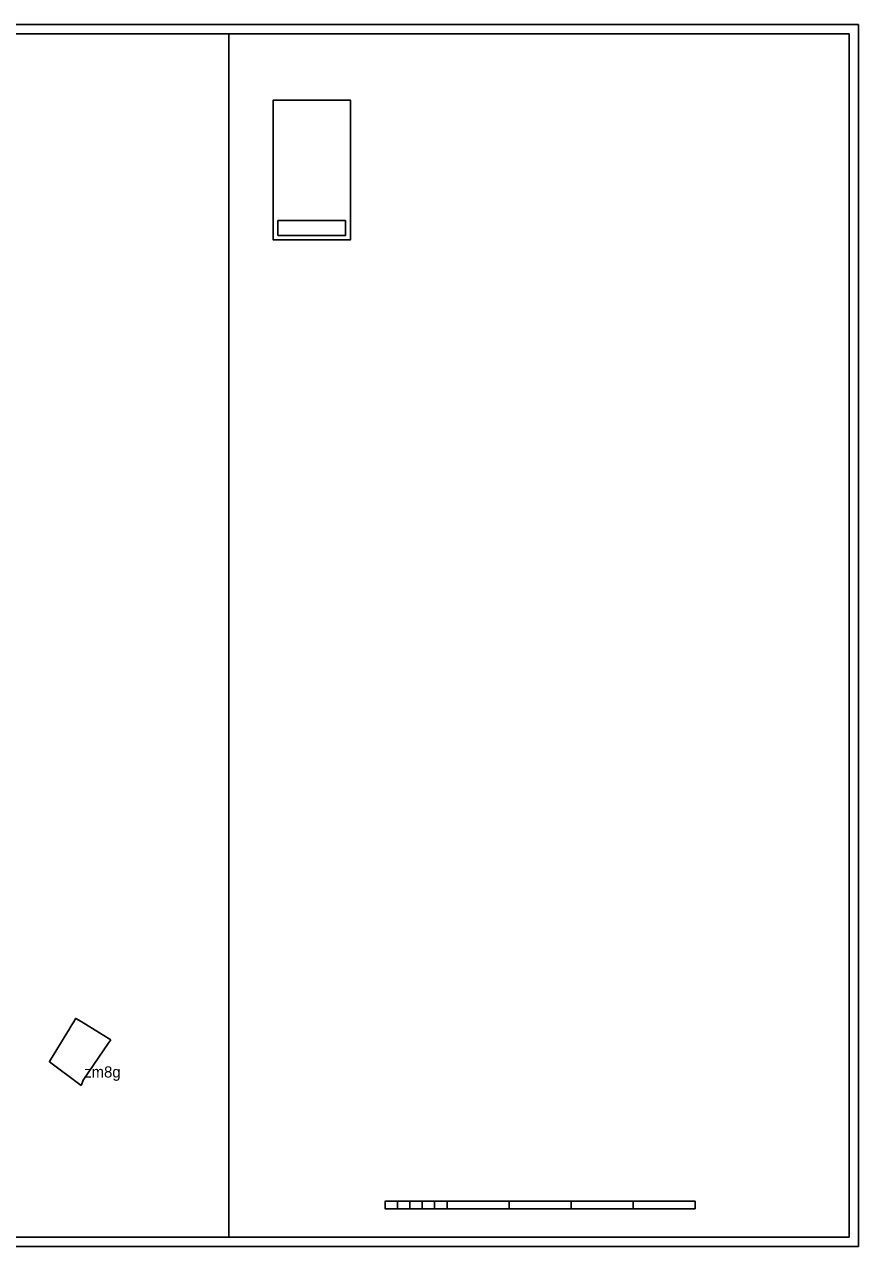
# Model space of a CAD drawing. Extents: x -555210 to -552521, y -1185897 to -1183927.
# Drawn here: x -553865 to -552521, y -1185897 to -1183927 of the extents above; entities that cross this region are included whole.
import ezdxf

# ---------------------------------------------------------------- set-up
doc = ezdxf.new("R2010")
doc.units = 0
for name, color, linetype in [('ram_5000', 7, 'Continuous'), ('stav_AP', 7, 'Continuous'), ('stav_OV', 7, 'Continuous'), ('stav_SV', 7, 'Continuous')]:
    doc.layers.add(name, color=color, linetype=linetype)

msp = doc.modelspace()

# ---------------------------------------------------------------- linework, layer by layer
at = {"layer": 'ram_5000'}
for p, q in [((-553790.4, -1185542.5), (-553794.4, -1185549)), ((-553790, -1185541.7), (-553790.4, -1185542.5)), ((-553784.8, -1185533.4), (-553790, -1185541.7)), ((-553782.8, -1185529.9), (-553784.8, -1185533.4)), ((-553782.5, -1185529.4), (-553782.8, -1185529.9)), ((-553773.9, -1185534.6), (-553782.5, -1185529.4)), ((-553726, -1185563.8), (-553773.9, -1185534.6)), ((-553795.5, -1185550.8), (-553824.8, -1185598.8)), ((-553794.4, -1185549), (-553795.5, -1185550.8)), ((-553770.8, -1185628.8), (-553729.2, -1185568.4)), ((-553729.2, -1185568.4), (-553726, -1185563.8)), ((-553824.8, -1185598.8), (-553825.1, -1185599.3)), ((-553825.1, -1185599.3), (-553773.8, -1185637.9)), ((-553773.8, -1185637.9), (-553771.9, -1185632.1)), ((-553771.9, -1185632.1), (-553770.8, -1185628.8))]:
    msp.add_line(p, q, dxfattribs=at)
at = {"layer": 'stav_AP'}
for p, q in [((-553456.9, -1184243.2), (-553456.9, -1184267.5)), ((-553403.6, -1184243.2), (-553456.9, -1184243.2)), ((-553456.9, -1184243.2), (-553456.9, -1184267.5)), ((-553403.6, -1184243.2), (-553456.9, -1184243.2)), ((-553456.9, -1184243.2), (-553456.9, -1184267.5)), ((-553403.6, -1184243.2), (-553456.9, -1184243.2))]:
    msp.add_line(p, q, dxfattribs=at)
for points in [[(-553456.9, -1184267.5), (-553347.9, -1184267.5), (-553347.9, -1184243.2)], [(-553456.9, -1184267.5), (-553347.9, -1184267.5), (-553347.9, -1184243.2)], [(-553456.9, -1184267.5), (-553347.9, -1184267.5), (-553347.9, -1184243.2)], [(-553347.9, -1184243.2), (-553399.6, -1184243.2), (-553403.6, -1184243.2)], [(-553347.9, -1184243.2), (-553399.6, -1184243.2), (-553403.6, -1184243.2)], [(-553347.9, -1184243.2), (-553399.6, -1184243.2), (-553403.6, -1184243.2)]]:
    msp.add_lwpolyline(points, dxfattribs=at)
at = {"layer": 'stav_OV'}
for p, q in [((-552520.8, -1183927), (-555209.8, -1183927)), ((-552520.8, -1185897.3), (-552520.8, -1183927)), ((-555194.8, -1183942), (-553535.8, -1183942)), ((-552535.8, -1183942), (-553535.8, -1183942)), ((-553535.8, -1183942), (-553535.8, -1185882.3)), ((-553535.8, -1183942), (-552535.8, -1183942)), ((-552535.8, -1185882.3), (-552535.8, -1183942)), ((-552535.8, -1183942), (-552535.8, -1185882.3)), ((-553464.5, -1184049.1), (-553339.5, -1184049.1)), ((-553464.5, -1184058.2), (-553464.5, -1184049.1)), ((-553464.5, -1184086.6), (-553464.5, -1184077.5)), ((-553464.5, -1184077.5), (-553464.5, -1184086.6)), ((-553464.5, -1184105.4), (-553464.5, -1184086.6)), ((-553464.5, -1184086.6), (-553464.5, -1184105.4)), ((-553464.5, -1184124.1), (-553464.5, -1184105.4)), ((-553464.5, -1184105.4), (-553464.5, -1184124.1)), ((-553464.5, -1184161.6), (-553464.5, -1184124.1)), ((-553464.5, -1184124.1), (-553464.5, -1184124.1)), ((-553464.5, -1184124.1), (-553464.5, -1184161.6)), ((-553464.5, -1184124.1), (-553464.5, -1184124.1)), ((-553464.5, -1184199.1), (-553464.5, -1184161.6)), ((-553464.5, -1184161.6), (-553464.5, -1184199.1)), ((-553339.5, -1184161.6), (-553339.5, -1184199.1)), ((-553339.5, -1184199.1), (-553339.5, -1184161.6)), ((-553464.5, -1184236.6), (-553464.5, -1184199.1)), ((-553339.5, -1184199.1), (-553339.5, -1184236.6)), ((-553244.1, -1185824.3), (-553264.1, -1185824.3)), ((-553264.1, -1185824.3), (-553264.1, -1185836.3)), ((-553264.1, -1185836.3), (-553244.1, -1185836.3)), ((-553244.1, -1185836.3), (-553244.1, -1185824.3)), ((-553204.1, -1185824.3), (-553224.1, -1185824.3)), ((-553224.1, -1185824.3), (-553224.1, -1185836.3)), ((-553224.1, -1185836.3), (-553204.1, -1185836.3)), ((-553204.1, -1185836.3), (-553204.1, -1185824.3)), ((-553084.1, -1185824.3), (-553184.1, -1185824.3)), ((-553184.1, -1185824.3), (-553184.1, -1185836.3)), ((-553184.1, -1185836.3), (-553084.1, -1185836.3)), ((-553084.1, -1185836.3), (-553084.1, -1185824.3)), ((-552884.1, -1185824.3), (-552984.1, -1185824.3)), ((-552984.1, -1185824.3), (-552984.1, -1185836.3)), ((-552984.1, -1185836.3), (-552884.1, -1185836.3)), ((-552884.1, -1185824.3), (-552784.1, -1185824.3)), ((-552884.1, -1185836.3), (-552884.1, -1185824.3)), ((-552784.1, -1185824.3), (-552784.1, -1185836.3)), ((-555209.8, -1185897.3), (-552520.8, -1185897.3)), ((-553535.8, -1185882.3), (-555194.8, -1185882.3)), ((-553535.8, -1185882.3), (-552535.8, -1185882.3)), ((-552535.8, -1185882.3), (-553535.8, -1185882.3))]:
    msp.add_line(p, q, dxfattribs=at)
for points in [[(-553339.5, -1184086.6), (-553339.5, -1184077.5), (-553339.5, -1184049.1), (-553464.5, -1184049.1), (-553464.5, -1184058.2)], [(-553464.5, -1184077.5), (-553464.5, -1184077.5), (-553464.5, -1184058.2)], [(-553464.5, -1184058.2), (-553464.5, -1184077.5), (-553464.5, -1184077.5)], [(-553339.5, -1184049.1), (-553339.5, -1184077.5), (-553339.5, -1184086.6)], [(-553339.5, -1184086.6), (-553339.5, -1184105.4), (-553339.5, -1184124.1)], [(-553339.5, -1184124.1), (-553339.5, -1184105.4), (-553339.5, -1184086.6)], [(-553339.5, -1184124.1), (-553339.5, -1184124.1), (-553339.5, -1184161.6)], [(-553339.5, -1184161.6), (-553339.5, -1184124.1), (-553339.5, -1184124.1)], [(-553464.5, -1184199.1), (-553464.5, -1184236.6), (-553464.5, -1184274.1), (-553339.5, -1184274.1), (-553339.5, -1184236.6), (-553339.5, -1184199.1)], [(-553339.5, -1184236.6), (-553339.5, -1184274.1), (-553464.5, -1184274.1), (-553464.5, -1184236.6)], [(-553264.1, -1185836.3), (-553284.1, -1185836.3), (-553284.1, -1185824.3), (-553264.1, -1185824.3)], [(-553264.1, -1185824.3), (-553244.1, -1185824.3), (-553224.1, -1185824.3), (-553204.1, -1185824.3), (-553184.1, -1185824.3), (-553084.1, -1185824.3), (-552984.1, -1185824.3), (-552884.1, -1185824.3)], [(-552784.1, -1185836.3), (-552884.1, -1185836.3), (-552984.1, -1185836.3), (-553084.1, -1185836.3), (-553184.1, -1185836.3), (-553204.1, -1185836.3), (-553224.1, -1185836.3), (-553244.1, -1185836.3), (-553264.1, -1185836.3)]]:
    msp.add_lwpolyline(points, dxfattribs=at)

# ---------------------------------------------------------------- texts
at = {"layer": 'stav_SV'}
msp.add_text('zm8g', height=18, dxfattribs=at).set_placement((-553769.1, -1185624.8))

doc.saveas('drawing.dxf')
